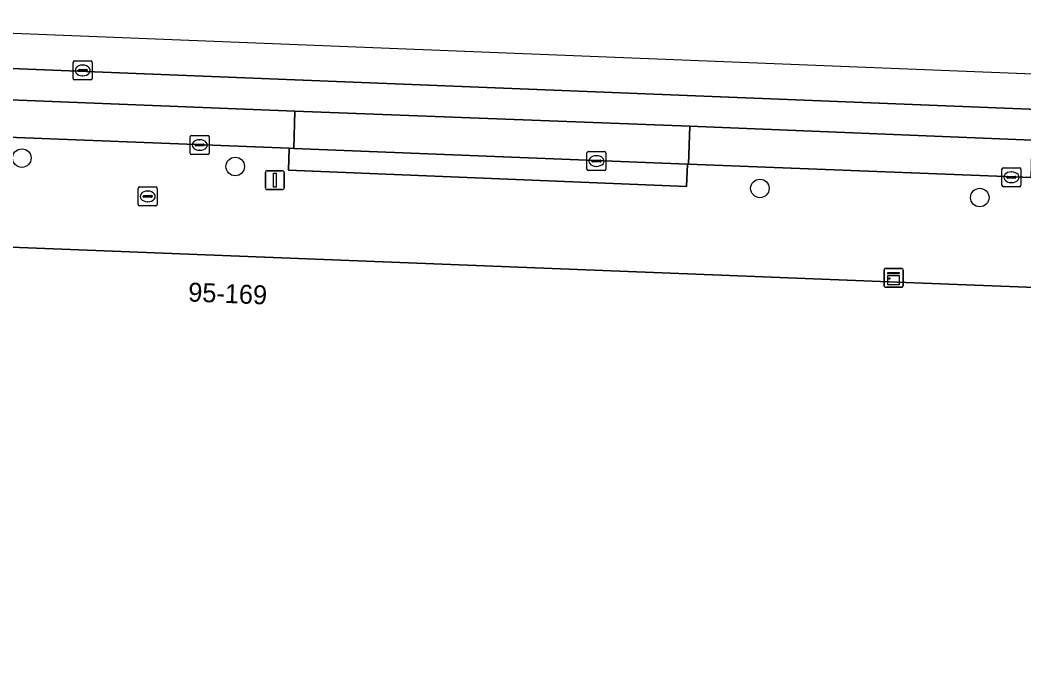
# Model space of a CAD drawing. Extents: x 160888 to 161385, y 386490 to 386908.
# Drawn here: x 161141.4 to 161194.4, y 386868.1 to 386902.4 of the extents above; entities that cross this region are included whole.
import ezdxf

# ---------------------------------------------------------------- set-up
doc = ezdxf.new("R2010")
doc.units = 0
for name, color, linetype in [('IMGEO_Boom', 7, 'Continuous'), ('IMGEO_Brandkraan', 7, 'Continuous'), ('IMGEO_Kast', 7, 'Continuous'), ('IMGEO_Kolk', 7, 'Continuous'), ('IMGEO_Lichtmast', 7, 'Continuous'), ('IMGEO_Pand', 7, 'Continuous'), ('IMGEO_Pand_nummerreeks', 7, 'Continuous'), ('IMGEO_Parkeervlak_gesloten', 7, 'Continuous'), ('IMGEO_Rijbaan_lokaal_gesloten', 7, 'Continuous'), ('IMGEO_Rioolput', 7, 'Continuous'), ('IMGEO_Voetpad_open', 7, 'Continuous')]:
    doc.layers.add(name, color=color, linetype=linetype)

msp = doc.modelspace()

# ---------------------------------------------------------------- linework, layer by layer
at = {"layer": 'IMGEO_Boom'}
for centre in [(161141.488, 386895.12), (161152.761, 386894.677), (161180.477, 386893.518), (161192.094, 386893.037)]:
    msp.add_circle(centre, 0.489, dxfattribs=at)
at = {"layer": 'IMGEO_Brandkraan'}
for p, q in [((161147.635, 386892.671), (161147.635, 386893.523)), ((161147.71, 386893.597), (161148.562, 386893.597)), ((161147.894, 386893.091), (161147.894, 386893.103)), ((161147.937, 386893.14), (161148.335, 386893.14)), ((161148.123, 386893.377), (161148.148, 386893.377)), ((161148.378, 386893.103), (161148.378, 386893.091)), ((161148.636, 386893.523), (161148.636, 386892.671)), ((161148.562, 386892.597), (161147.71, 386892.597)), ((161148.332, 386893.054), (161147.934, 386893.054)), ((161148.146, 386892.817), (161148.121, 386892.817))]:
    msp.add_line(p, q, dxfattribs=at)
for points in [[(161147.635, 386892.671), (161147.635, 386893.523)], [(161147.71, 386893.597), (161148.562, 386893.597)], [(161148.636, 386893.523), (161148.636, 386892.671)], [(161148.562, 386892.597), (161147.71, 386892.597)]]:
    msp.add_lwpolyline(points, dxfattribs=at)
for centre, radius, start, end in [((161147.712, 386893.521), 0.0765, 91.552, 178.448), ((161147.712, 386893.521), 0.0765, 91.552, 178.448), ((161147.934, 386893.1), 0.0403, 85.8775, 175.7526), ((161147.931, 386893.09), 0.0366, 178.938, 274.7102), ((161148.335, 386893.097), 0.043, 264.8664, 352.4533), ((161148.339, 386893.102), 0.0386, 1.7309, 96.639), ((161148.56, 386893.521), 0.0765, 1.552, 88.448), ((161148.56, 386893.521), 0.0765, 1.552, 88.448), ((161147.712, 386892.673), 0.0765, 181.552, 268.448), ((161147.712, 386892.673), 0.0765, 181.552, 268.448), ((161148.56, 386892.673), 0.0765, 271.552, 358.448), ((161148.56, 386892.673), 0.0765, 271.552, 358.448)]:
    msp.add_arc(centre, radius, start, end, dxfattribs=at)
for centre, major_axis, ratio, start_param, end_param in [((161148.122, 386893.097), (-0.387, 0.002), 0.722429, 4.712389, 7.853982), ((161148.147, 386893.097), (-0.39, 0.002), 0.717154, 1.570796, 4.712389)]:
    msp.add_ellipse(centre, major_axis=major_axis, ratio=ratio, start_param=start_param, end_param=end_param, dxfattribs=at)
at = {"layer": 'IMGEO_Kast'}
for p, q in [((161187.04, 386888.371), (161187.04, 386889.212)), ((161187.04, 386889.212), (161187.04, 386888.371)), ((161187.115, 386889.296), (161187.956, 386889.296)), ((161187.956, 386889.296), (161187.115, 386889.296)), ((161188.04, 386889.221), (161188.04, 386888.38)), ((161188.04, 386888.38), (161188.04, 386889.221)), ((161187.965, 386888.296), (161187.124, 386888.296)), ((161187.124, 386888.296), (161187.965, 386888.296))]:
    msp.add_line(p, q, dxfattribs=at)
for points in [[(161187.235, 386889.086), (161187.835, 386889.086), (161187.835, 386889.001), (161187.235, 386889.001), (161187.235, 386889.086)], [(161187.235, 386888.911), (161187.835, 386888.911), (161187.835, 386888.422), (161187.235, 386888.422), (161187.235, 386888.911)]]:
    msp.add_lwpolyline(points, dxfattribs=at)
msp.add_circle((161187.319, 386888.76), 0.0377, dxfattribs=at)
for centre, start, end in [((161187.118, 386889.218), 92.4484, 184.2845), ((161187.118, 386889.218), 92.4484, 184.2845), ((161187.962, 386889.218), 2.4484, 94.2845), ((161187.962, 386889.218), 2.4484, 94.2845), ((161187.118, 386888.374), 182.4484, 274.2845), ((161187.118, 386888.374), 182.4484, 274.2845), ((161187.962, 386888.374), 272.4484, 4.2845), ((161187.962, 386888.374), 272.4484, 4.2845)]:
    msp.add_arc(centre, 0.0779, start, end, dxfattribs=at)
at = {"layer": 'IMGEO_Kolk'}
for p, q in [((161150.458, 386896.311), (161151.31, 386896.311)), ((161150.383, 386895.385), (161150.383, 386896.237)), ((161150.642, 386895.805), (161150.642, 386895.817)), ((161151.08, 386895.768), (161150.682, 386895.768)), ((161150.685, 386895.854), (161151.083, 386895.854)), ((161150.871, 386896.091), (161150.896, 386896.091)), ((161151.126, 386895.817), (161151.126, 386895.805)), ((161151.384, 386896.237), (161151.384, 386895.385)), ((161151.31, 386895.311), (161150.458, 386895.311)), ((161150.894, 386895.531), (161150.869, 386895.531)), ((161171.341, 386894.538), (161171.341, 386895.39)), ((161171.416, 386895.464), (161172.268, 386895.464)), ((161171.829, 386895.244), (161171.854, 386895.244)), ((161172.342, 386895.39), (161172.342, 386894.538)), ((161171.6, 386894.958), (161171.6, 386894.97)), ((161172.038, 386894.921), (161171.64, 386894.921)), ((161171.643, 386895.007), (161172.041, 386895.007)), ((161171.852, 386894.684), (161171.827, 386894.684)), ((161172.084, 386894.97), (161172.084, 386894.958)), ((161172.268, 386894.464), (161171.416, 386894.464)), ((161193.264, 386893.682), (161193.264, 386894.534)), ((161193.339, 386894.608), (161194.191, 386894.608)), ((161193.566, 386894.151), (161193.964, 386894.151)), ((161193.752, 386894.388), (161193.777, 386894.388)), ((161194.265, 386894.534), (161194.265, 386893.682)), ((161194.191, 386893.608), (161193.339, 386893.608)), ((161193.523, 386894.102), (161193.523, 386894.114)), ((161193.961, 386894.065), (161193.563, 386894.065)), ((161193.775, 386893.828), (161193.75, 386893.828)), ((161194.007, 386894.114), (161194.007, 386894.102))]:
    msp.add_line(p, q, dxfattribs=at)
for points in [[(161150.458, 386896.311), (161151.31, 386896.311)], [(161150.383, 386895.385), (161150.383, 386896.237)], [(161151.384, 386896.237), (161151.384, 386895.385)], [(161151.31, 386895.311), (161150.458, 386895.311)], [(161171.341, 386894.538), (161171.341, 386895.39)], [(161171.416, 386895.464), (161172.268, 386895.464)], [(161172.342, 386895.39), (161172.342, 386894.538)], [(161172.268, 386894.464), (161171.416, 386894.464)], [(161193.264, 386893.682), (161193.264, 386894.534)], [(161193.339, 386894.608), (161194.191, 386894.608)], [(161194.265, 386894.534), (161194.265, 386893.682)], [(161194.191, 386893.608), (161193.339, 386893.608)]]:
    msp.add_lwpolyline(points, dxfattribs=at)
for centre, radius, start, end in [((161150.46, 386896.235), 0.0765, 91.552, 178.448), ((161150.46, 386896.235), 0.0765, 91.552, 178.448), ((161151.308, 386896.235), 0.0765, 1.552, 88.448), ((161151.308, 386896.235), 0.0765, 1.552, 88.448), ((161150.682, 386895.814), 0.0403, 85.8775, 175.7526), ((161150.679, 386895.804), 0.0366, 178.938, 274.7102), ((161151.083, 386895.811), 0.043, 264.8664, 352.4533), ((161151.087, 386895.816), 0.0386, 1.7309, 96.639), ((161150.46, 386895.387), 0.0765, 181.552, 268.448), ((161150.46, 386895.387), 0.0765, 181.552, 268.448), ((161151.308, 386895.387), 0.0765, 271.552, 358.448), ((161151.308, 386895.387), 0.0765, 271.552, 358.448), ((161171.418, 386895.388), 0.0765, 91.552, 178.448), ((161171.418, 386895.388), 0.0765, 91.552, 178.448), ((161172.266, 386895.388), 0.0765, 1.552, 88.448), ((161172.266, 386895.388), 0.0765, 1.552, 88.448), ((161171.64, 386894.967), 0.0403, 85.8775, 175.7526), ((161171.637, 386894.957), 0.0366, 178.938, 274.7102), ((161172.041, 386894.964), 0.043, 264.8664, 352.4533), ((161172.045, 386894.969), 0.0386, 1.7309, 96.639), ((161171.418, 386894.54), 0.0765, 181.552, 268.448), ((161171.418, 386894.54), 0.0765, 181.552, 268.448), ((161172.266, 386894.54), 0.0765, 271.552, 358.448), ((161172.266, 386894.54), 0.0765, 271.552, 358.448), ((161193.341, 386894.532), 0.0765, 91.552, 178.448), ((161193.341, 386894.532), 0.0765, 91.552, 178.448), ((161193.563, 386894.111), 0.0403, 85.8775, 175.7526), ((161193.968, 386894.113), 0.0386, 1.7309, 96.639), ((161194.189, 386894.532), 0.0765, 1.552, 88.448), ((161194.189, 386894.532), 0.0765, 1.552, 88.448), ((161193.341, 386893.684), 0.0765, 181.552, 268.448), ((161193.341, 386893.684), 0.0765, 181.552, 268.448), ((161193.56, 386894.101), 0.0366, 178.938, 274.7102), ((161193.964, 386894.108), 0.043, 264.8664, 352.4533), ((161194.189, 386893.684), 0.0765, 271.552, 358.448), ((161194.189, 386893.684), 0.0765, 271.552, 358.448)]:
    msp.add_arc(centre, radius, start, end, dxfattribs=at)
for centre, major_axis, ratio, start_param, end_param in [((161150.87, 386895.811), (-0.387, 0.002), 0.722429, 4.712389, 7.853982), ((161150.895, 386895.811), (-0.39, 0.002), 0.717154, 1.570796, 4.712389), ((161171.828, 386894.964), (-0.387, 0.002), 0.722429, 4.712389, 7.853982), ((161171.853, 386894.964), (-0.39, 0.002), 0.717154, 1.570796, 4.712389), ((161193.751, 386894.108), (-0.387, 0.002), 0.722429, 4.712389, 7.853982), ((161193.776, 386894.108), (-0.39, 0.002), 0.717154, 1.570796, 4.712389)]:
    msp.add_ellipse(centre, major_axis=major_axis, ratio=ratio, start_param=start_param, end_param=end_param, dxfattribs=at)
at = {"layer": 'IMGEO_Lichtmast'}
for p, q in [((161154.355, 386893.555), (161154.355, 386894.355)), ((161154.355, 386894.355), (161154.355, 386893.555)), ((161154.455, 386894.455), (161155.245, 386894.455)), ((161155.245, 386894.455), (161154.455, 386894.455)), ((161155.345, 386894.355), (161155.345, 386893.555)), ((161155.345, 386893.555), (161155.345, 386894.355)), ((161155.245, 386893.455), (161154.455, 386893.455)), ((161154.455, 386893.455), (161155.245, 386893.455))]:
    msp.add_line(p, q, dxfattribs=at)
msp.add_lwpolyline([(161154.775, 386894.33), (161154.925, 386894.33), (161154.925, 386893.58), (161154.775, 386893.58), (161154.775, 386894.33)], dxfattribs=at)
for centre, start, end in [((161154.455, 386894.355), 90, 180), ((161154.455, 386894.355), 90, 180), ((161155.245, 386894.355), 0, 90), ((161155.245, 386894.355), 360, 90), ((161154.455, 386893.555), 180, 270), ((161154.455, 386893.555), 180, 270), ((161155.245, 386893.555), 270, 0), ((161155.245, 386893.555), 270, 0)]:
    msp.add_arc(centre, 0.1, start, end, dxfattribs=at)
at = {"layer": 'IMGEO_Pand'}
msp.add_lwpolyline([(161120.067, 386845.369), (161194.586, 386842.427), (161196.377, 386887.78), (161196.381, 386887.886), (161196.395, 386888.23), (161188.186, 386888.554), (161178.427, 386888.94), (161127.058, 386890.969), (161126.941, 386888.577), (161126.862, 386886.972), (161123.715, 386887.092), (161123.545, 386882.788), (161121.567, 386882.869), (161121.073, 386870.746), (161120.711, 386870.76), (161120.682, 386870.014), (161121.042, 386870), (161120.551, 386857.609)], close=True, dxfattribs=at)
at = {"layer": 'IMGEO_Parkeervlak_gesloten'}
for points in [[(161155.904, 386897.594), (161123.188, 386898.901), (161122.96, 386898.916), (161122.897, 386898.919), (161123.175, 386898.874)], [(161125.921, 386896.787), (161127.859, 386896.678), (161137.577, 386896.347), (161155.616, 386895.637), (161155.851, 386895.628), (161155.904, 386897.594)]]:
    msp.add_lwpolyline(points, dxfattribs=at)
msp.add_lwpolyline([(161194.86, 386896.072), (161176.778, 386896.8), (161176.703, 386894.8), (161194.801, 386894.087)], close=True, dxfattribs=at)
at = {"layer": 'IMGEO_Rijbaan_lokaal_gesloten'}
msp.add_lwpolyline([(161291.165, 386895.721), (161123.374, 386902.409), (161123.263, 386900.56), (161248.069, 386895.57), (161278.544, 386894.358), (161279.11, 386894.349), (161286.088, 386894.243)], dxfattribs=at)
for points in [[(161279.11, 386894.349), (161278.544, 386894.358), (161248.069, 386895.57), (161123.263, 386900.56), (161123.188, 386898.901), (161155.904, 386897.594), (161176.778, 386896.8), (161194.86, 386896.072), (161209.056, 386895.484), (161221.008, 386894.938), (161241.882, 386894.123), (161247.927, 386893.867), (161258.887, 386893.342), (161276.971, 386892.717), (161277.593, 386892.717), (161277.832, 386892.705), (161279.059, 386892.659)], [(161176.778, 386896.8), (161155.904, 386897.594), (161155.851, 386895.628), (161176.66, 386894.802), (161176.703, 386894.8)]]:
    msp.add_lwpolyline(points, close=True, dxfattribs=at)
at = {"layer": 'IMGEO_Rioolput'}
for p, q in [((161144.202, 386899.324), (161144.202, 386900.176)), ((161144.277, 386900.25), (161145.129, 386900.25)), ((161144.69, 386900.03), (161144.715, 386900.03)), ((161145.203, 386900.176), (161145.203, 386899.324)), ((161144.461, 386899.744), (161144.461, 386899.756)), ((161144.899, 386899.707), (161144.501, 386899.707)), ((161144.504, 386899.793), (161144.902, 386899.793)), ((161144.713, 386899.47), (161144.688, 386899.47)), ((161144.945, 386899.756), (161144.945, 386899.744)), ((161145.129, 386899.25), (161144.277, 386899.25))]:
    msp.add_line(p, q, dxfattribs=at)
for points in [[(161144.202, 386899.324), (161144.202, 386900.176)], [(161144.277, 386900.25), (161145.129, 386900.25)], [(161145.203, 386900.176), (161145.203, 386899.324)], [(161145.129, 386899.25), (161144.277, 386899.25)]]:
    msp.add_lwpolyline(points, dxfattribs=at)
for centre, radius, start, end in [((161144.279, 386900.174), 0.0765, 91.552, 178.448), ((161144.279, 386900.174), 0.0765, 91.552, 178.448), ((161145.127, 386900.174), 0.0765, 1.552, 88.448), ((161145.127, 386900.174), 0.0765, 1.552, 88.448), ((161144.501, 386899.753), 0.0403, 85.8775, 175.7526), ((161144.498, 386899.743), 0.0366, 178.938, 274.7102), ((161144.902, 386899.75), 0.043, 264.8664, 352.4533), ((161144.906, 386899.755), 0.0386, 1.7309, 96.639), ((161144.279, 386899.326), 0.0765, 181.552, 268.448), ((161144.279, 386899.326), 0.0765, 181.552, 268.448), ((161145.127, 386899.326), 0.0765, 271.552, 358.448), ((161145.127, 386899.326), 0.0765, 271.552, 358.448)]:
    msp.add_arc(centre, radius, start, end, dxfattribs=at)
for centre, major_axis, ratio, start_param, end_param in [((161144.689, 386899.75), (-0.387, 0.002), 0.722429, 4.712389, 7.853982), ((161144.714, 386899.75), (-0.39, 0.002), 0.717154, 1.570796, 4.712389)]:
    msp.add_ellipse(centre, major_axis=major_axis, ratio=ratio, start_param=start_param, end_param=end_param, dxfattribs=at)
at = {"layer": 'IMGEO_Voetpad_open'}
for points in [[(161155.616, 386895.637), (161137.577, 386896.347), (161127.859, 386896.678), (161125.921, 386896.787)], [(161274.2, 386890.804), (161258.81, 386891.423), (161256.885, 386891.501), (161256.805, 386890.402), (161250.217, 386890.662), (161250.255, 386891.79), (161247.831, 386891.89), (161241.794, 386892.138), (161239.425, 386892.236), (161239.41, 386891.107), (161235.397, 386891.29), (161235.468, 386892.398), (161220.937, 386892.996), (161208.945, 386893.49), (161207.063, 386893.567), (161206.996, 386892.136), (161196.74, 386892.515), (161196.781, 386894.009), (161194.801, 386894.087), (161176.703, 386894.8), (161176.66, 386894.802), (161176.601, 386893.617), (161155.57, 386894.474), (161155.616, 386895.637)], [(161127.058, 386890.969), (161178.427, 386888.94), (161188.186, 386888.554), (161196.395, 386888.23), (161196.381, 386887.886), (161205.414, 386887.602), (161205.385, 386886.913), (161206.029, 386886.888), (161210.581, 386886.706), (161222.369, 386886.248), (161222.396, 386887.248), (161239.793, 386886.567), (161249.896, 386886.171), (161268.594, 386885.414), (161278.689, 386885.003), (161279.034, 386891.63), (161279.059, 386892.659), (161277.832, 386892.705), (161277.593, 386892.717)]]:
    msp.add_lwpolyline(points, dxfattribs=at)
msp.add_lwpolyline([(161176.66, 386894.802), (161155.851, 386895.628), (161155.616, 386895.637), (161155.57, 386894.474), (161176.601, 386893.617)], close=True, dxfattribs=at)

# ---------------------------------------------------------------- texts
at = {"layer": 'IMGEO_Pand_nummerreeks'}
msp.add_text('95-169', height=1, rotation=357.7381, dxfattribs=at).set_placement((161150.263, 386887.55))

doc.saveas('drawing.dxf')
